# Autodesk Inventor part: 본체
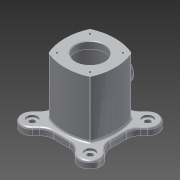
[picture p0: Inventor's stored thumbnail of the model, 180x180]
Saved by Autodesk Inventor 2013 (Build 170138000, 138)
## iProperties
Created: 2016-05
Part Number: 본체
Material: 알루미늄 6061
Document SubType Name: Modeling
Designer: Administrator
Density: 2.71 g/cm^3
Mass: 1110.84 g
Surface Area: 862.718 cm^2
Volume: 409.905 cm^3
Author: Administrator
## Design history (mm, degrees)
sketch "스케치1"
  geometry: L1 (-35.355, 35.355)-(35.355, 35.355); L2 (35.355, 35.355)-(35.355, -35.355); L3 (35.355, -35.355)-(-35.355, -35.355); L4 (-35.355, -35.355)-(-35.355, 35.355); L5 (-35.355, 35.355)-(35.355, -35.355); L6 (35.355, 35.355)-(-35.355, -35.355); A1 r 85.579 centre (0, -42.579) between (35.355, 35.355) and (-35.355, 35.355); A2 r 85.579 centre (0, 42.579) between (-35.355, -35.355) and (35.355, -35.355); A3 r 85.579 centre (-42.579, 0) between (35.355, -35.355) and (35.355, 35.355); A4 r 85.579 centre (42.579, 0) between (-35.355, 35.355) and (-35.355, -35.355); 3 further points
  constraints: 12 end point, 8 point on circle, 4 centre point, 3 equal radius, 3 midpoint, 2 parallel, 1 coincident, 1 horizontal, 1 perpendicular
  dimensions: "d1" = 86 dimension on A2 A1; "d3" = 100 distance of L2.end L1.start; "d4" = 86 dimension on A3 A4; "d5" = 100 distance of L1.end L3.end (derived)
extrude "돌출1" new body sketch "스케치1" distance "d6" = 98; taper "d7" = 0 deg
sketch "스케치2" dims "d88" = 140
  geometry: L1 (0, 0)-(0, 85.235); L2 (0, 0)-(-90.797, 90.797); L3 (-36.77, 62.225)-(-23.544, 49); L4 (-49, 23.544)-(-62.225, 36.77); L5 (-49, 49)-(49, 49); L6 (49, 49)-(49, -49); L7 (49, -49)-(-49, -49); L8 (-49, -49)-(-49, 49); L9 (-49, 49)-(49, -49); L10 (49, 49)-(-49, -49); L11 (36.77, 62.225)-(23.544, 49); L12 (49, 23.544)-(62.225, 36.77); L13 (0, 0)-(-78.622, 0); L14 (49, -23.544)-(62.225, -36.77); L15 (36.77, -62.225)-(23.544, -49); L16 (-36.77, -62.225)-(-23.544, -49); L17 (-49, -23.544)-(-62.225, -36.77); L18 (-49, 23.544)-(-49, -23.544); L19 (-23.544, -49)-(23.544, -49); L20 (49, -23.544)-(49, 23.544); L21 (23.544, 49)-(-23.544, 49); A1 r 18 centre (-49.497, 49.497) between (-36.77, 62.225) and (-62.225, 36.77); A2 r 18 centre (49.497, 49.497) between (36.77, 62.225) and (62.225, 36.77); A3 r 18 centre (49.497, -49.497) between (36.77, -62.225) and (62.225, -36.77); A4 r 18 centre (-49.497, -49.497) between (-36.77, -62.225) and (-62.225, -36.77); 3 further points
  constraints: 42 end point, 15 symmetric about line, 8 point on circle, 6 point on line, 5 parallel, 4 centre point, 3 perpendicular, 2 collinear, 2 midpoint, 1 coincident, 1 horizontal, 1 vertical, 6 other
  dimensions: "d90" = 45 deg angle of L2 L1; "d92" = 36 diameter of A1; "d93" = 18 distance between parallel lines of L4 L2; "d94" = 18 distance between parallel lines of L3 L2; "d95" = 98 distance of L5.start L5.end
extrude "돌출2" join sketch "스케치2" distance "d15" = 12; taper "d16" = 0 deg
sketch "스케치3"
  geometry: L1 (-60.523, 35.171)-(-49, 23.649) reference; L2 (-49, 23.649)-(-49, -23.649) reference; L3 (-49, -23.649)-(-60.523, -35.171) reference; L4 (-35.171, -60.523)-(-23.649, -49) reference; L5 (-23.649, -49)-(23.649, -49) reference; L6 (23.649, -49)-(35.171, -60.523) reference; L7 (60.523, -35.171)-(49, -23.649) reference; L8 (49, -23.649)-(49, 23.649) reference; L9 (49, 23.649)-(60.523, 35.171) reference; L10 (35.171, 60.523)-(23.649, 49) reference; L11 (23.649, 49)-(-23.649, 49) reference; L12 (-23.649, 49)-(-35.171, 60.523) reference; A1 r 18 centre (-49, 49) between (-35.171, 60.523) and (-60.523, 35.171) reference; A2 r 18 centre (-49, -49) between (-60.523, -35.171) and (-35.171, -60.523) reference; A3 r 18 centre (49, -49) between (35.171, -60.523) and (60.523, -35.171) reference; A4 r 18 centre (49, 49) between (60.523, 35.171) and (35.171, 60.523) reference; 1 further point
node "작업 평면1"
sketch "스케치4"
  geometry: L1 (35.355, 98)-(-35.355, 98) reference; L2 (43, 0)-(43, 98) reference; L3 (23.544, 0)-(-23.544, 0) reference; C1 r 20 at (0, 49); 3 further points
  constraints: 2 vertical alignment, 1 centre point, 1 midpoint
  dimensions: "d19" = 40 diameter of C1; "d96" = 49 distance from line of C1.centre L3
extrude "돌출3" join sketch "스케치4" stored distance "d20" = 12; taper "d21" = 10 deg
sketch "스케치5"
  geometry: C1 r 20 at (0, 0) reference; 1 further point
hole "구멍1" sketch "스케치5" at (0, 0) diameter "d22" = 25; stored, may be unused: countersink angle "d26" = 90 deg, drill point angle "d28" = 118 deg; dims "d23" = 6, "d24" = 30, "d25" = 8, "d27" = 30
sketch "스케치6"
  geometry: C1 r 25 at (0, 0); 1 further point
  constraints: 1 centre point, 1 coincident
  dimensions: "d29" = 50 diameter of C1
extrude "돌출4" cut sketch "스케치6" distance "d31" = 12; taper "d32" = 0 deg
sketch "스케치7"
  geometry: C1 r 25 at (0, 0) reference
hole "구멍2" sketch "스케치7" at (0, 0) diameter "d33" = 50; stored, may be unused: countersink angle "d37" = 90 deg, drill point angle "d39" = 0 deg; dims "d34" = 6, "d35" = 70, "d36" = 86, "d38" = 98
sketch "스케치9"
  geometry: L1 (0, 0)-(-28.284, 28.284); L2 (0, 0)-(0, 61.728); C1 r 25 at (0, 0) reference
  constraints: 4 end point
  dimensions: "d47" = 40 distance of L1.start L1.end; "d48" = 45 deg angle of L1 L2
hole "구멍4" sketch "스케치9" at (-28.284, 28.284) diameter "d49" = 3.242; stored, may be unused: countersink angle "d53" = 90 deg, drill point angle "d55" = 118 deg; dims "d50" = 7, "d51" = 18, "d52" = 4, "d54" = 10
sketch "스케치10"
  geometry: L1 (0, 0)-(0, 75.036); L2 (0, 0)-(-28.284, 28.284); C1 r 25 at (0, 0) reference
  constraints: 4 end point, 1 vertical
  dimensions: "d59" = 45 deg angle of L2 L1; "d60" = 40 distance of L1.start L2.end
hole "구멍5" sketch "스케치10" at (-28.284, 28.284) diameter "d61" = 3.242; stored, may be unused: countersink angle "d65" = 90 deg, drill point angle "d67" = 118 deg; dims "d62" = 7, "d63" = 18, "d64" = 4, "d66" = 10
chamfer "모따기1" distance "d71" = 1; stored, may be unused: second distance "d72" = 2, angle "d73" = 45 deg
node "작업 평면2"
fillet "모깎기3" dims "d97" = 25, "d98" = 3
node "작업 평면3"
sketch "스케치12"
  geometry: 3 further points; 1 other entity
  constraints: 1 horizontal alignment, 2 other
feature "엠보싱1" sketch "스케치12" dims "d1" = 86, "d3" = 100, "d4" = 86, "d5" = 100 (derived), "d80" = 0.5, "d81" = 0
sketch "스케치13"
  geometry: L1 (-46, -13.189)-(-46, 0) reference; L2 (-60.104, -38.891)-(-54.201, -32.988) reference; L3 (-32.988, -54.201)-(-38.891, -60.104) reference; L4 (0, -46)-(-13.189, -46) reference; L5 (13.189, -46)-(0, -46) reference; L6 (38.891, -60.104)-(32.988, -54.201) reference; L7 (54.201, -32.988)-(60.104, -38.891) reference; L8 (46, 0)-(46, -13.189) reference; L9 (46, 13.189)-(46, 0) reference; L10 (60.104, 38.891)-(54.201, 32.988) reference; L11 (32.988, 54.201)-(38.891, 60.104) reference; L12 (0, 46)-(13.189, 46) reference; A1 r 15 centre (-49.497, 49.497) between (-38.891, 60.104) and (-60.104, 38.891) reference; A2 r 88.579 centre (42.579, 0) between (-46, 0) and (-38.581, -35.487) reference; A3 r 28 centre (-74, -13.189) between (-54.201, -32.988) and (-46, -13.189) reference; A4 r 15 centre (-49.497, -49.497) between (-60.104, -38.891) and (-38.891, -60.104) reference; A5 r 28 centre (-13.189, -74) between (-13.189, -46) and (-32.988, -54.201) reference; A6 r 88.579 centre (0, 42.579) between (-35.487, -38.581) and (0, -46) reference; A7 r 6 centre (-33.083, -33.083) between (-38.581, -35.487) and (-35.487, -38.581) reference; A8 r 88.579 centre (0, 42.579) between (0, -46) and (35.487, -38.581) reference; A9 r 28 centre (13.189, -74) between (32.988, -54.201) and (13.189, -46) reference; A10 r 15 centre (49.497, -49.497) between (38.891, -60.104) and (60.104, -38.891) reference; A11 r 28 centre (74, -13.189) between (46, -13.189) and (54.201, -32.988) reference; A12 r 88.579 centre (-42.579, 0) between (38.581, -35.487) and (46, 0) reference; A13 r 6 centre (33.083, -33.083) between (35.487, -38.581) and (38.581, -35.487) reference; A14 r 88.579 centre (0, -42.579) between (35.487, 38.581) and (0, 46) reference; A15 r 6 centre (33.083, 33.083) between (38.581, 35.487) and (35.487, 38.581) reference; A16 r 88.579 centre (-42.579, 0) between (46, 0) and (38.581, 35.487) reference; A17 r 28 centre (74, 13.189) between (54.201, 32.988) and (46, 13.189) reference; A18 r 15 centre (49.497, 49.497) between (60.104, 38.891) and (38.891, 60.104) reference; A19 r 28 centre (13.189, 74) between (13.189, 46) and (32.988, 54.201) reference; 1 further point
hole "구멍6" sketch "스케치13" at (-49.497, 49.497), (49.497, 49.497), (49.497, -49.497), (-49.497, -49.497) diameter "d99" = 10; stored, may be unused: countersink angle "d103" = 90 deg, drill point angle "d105" = 118 deg; dims "d100" = 6, "d101" = 18, "d102" = 4, "d104" = 8
node "솔리드1"
pattern_circular "원형 패턴1" dims angle "d57" = 360 deg
pattern_circular "원형 패턴2" dims angle "d69" = 360 deg
sketch "스케치11"
  geometry: L1 (0, 0)-(29, 37.937); 1 further point
  constraints: 2 end point
  dimensions: "d78" = 29 horizontal distance of L1.end point (0, -42.579)
node "투영된 루프1"
node "투영된 루프2"
node "투영된 루프3"
other parameters: "d17" = 55, "d77" = 49
